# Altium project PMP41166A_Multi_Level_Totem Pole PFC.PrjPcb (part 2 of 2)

## Sheet PMP41166A_Multi_Level_Totem Pole PFC_Control Card.SchDoc
size A2; Date: Not shown in title block; ApprovedBy: Not shown in title block; CheckedBy: Not shown in title block; Author: Not shown in title block; CompanyName: Not shown in title block; Engineer: Not shown in title block; Organization: Not shown in title block; Address1: Not shown in title block; Address2: Not shown in title block; Address3: Not shown in title block; Address4: Not shown in title block; DocumentNumber: 1; Revision: Use project parameter SCH_Rev; SheetNumber: 3; SheetTotal: 4; PageSetup: Record=PageOptions¦CenterHorizontal=True¦CenterVertical=True¦PrintScale=0.69¦XCorrection=1.00¦YCorrection=1.00¦PrintKind=0¦BorderSize=5000000¦LeftOffset=0¦BottomOffset=0¦Orientation=2¦PaperLength=1000¦PaperWidth=1000¦Scale=100¦PaperSource=15¦PrintQuality=600¦MediaType=1¦DitherType=10¦PaperKind=Letter¦PrintScaleMode=1
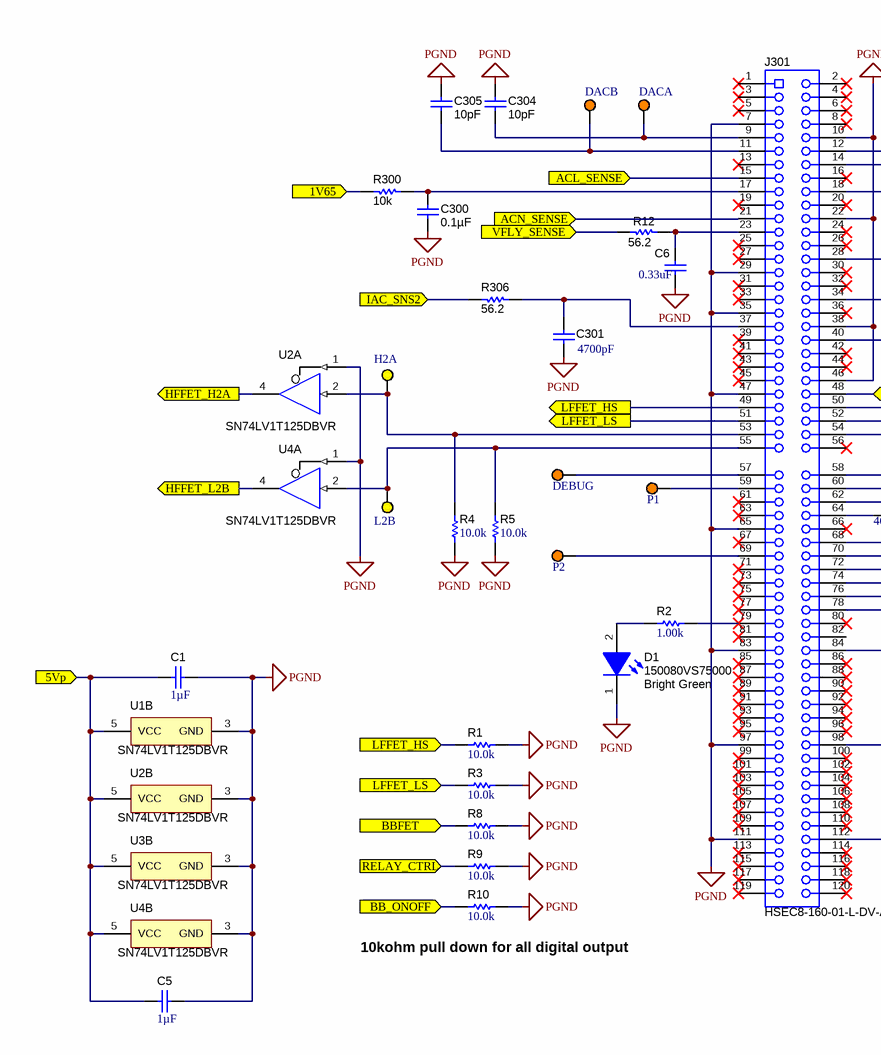
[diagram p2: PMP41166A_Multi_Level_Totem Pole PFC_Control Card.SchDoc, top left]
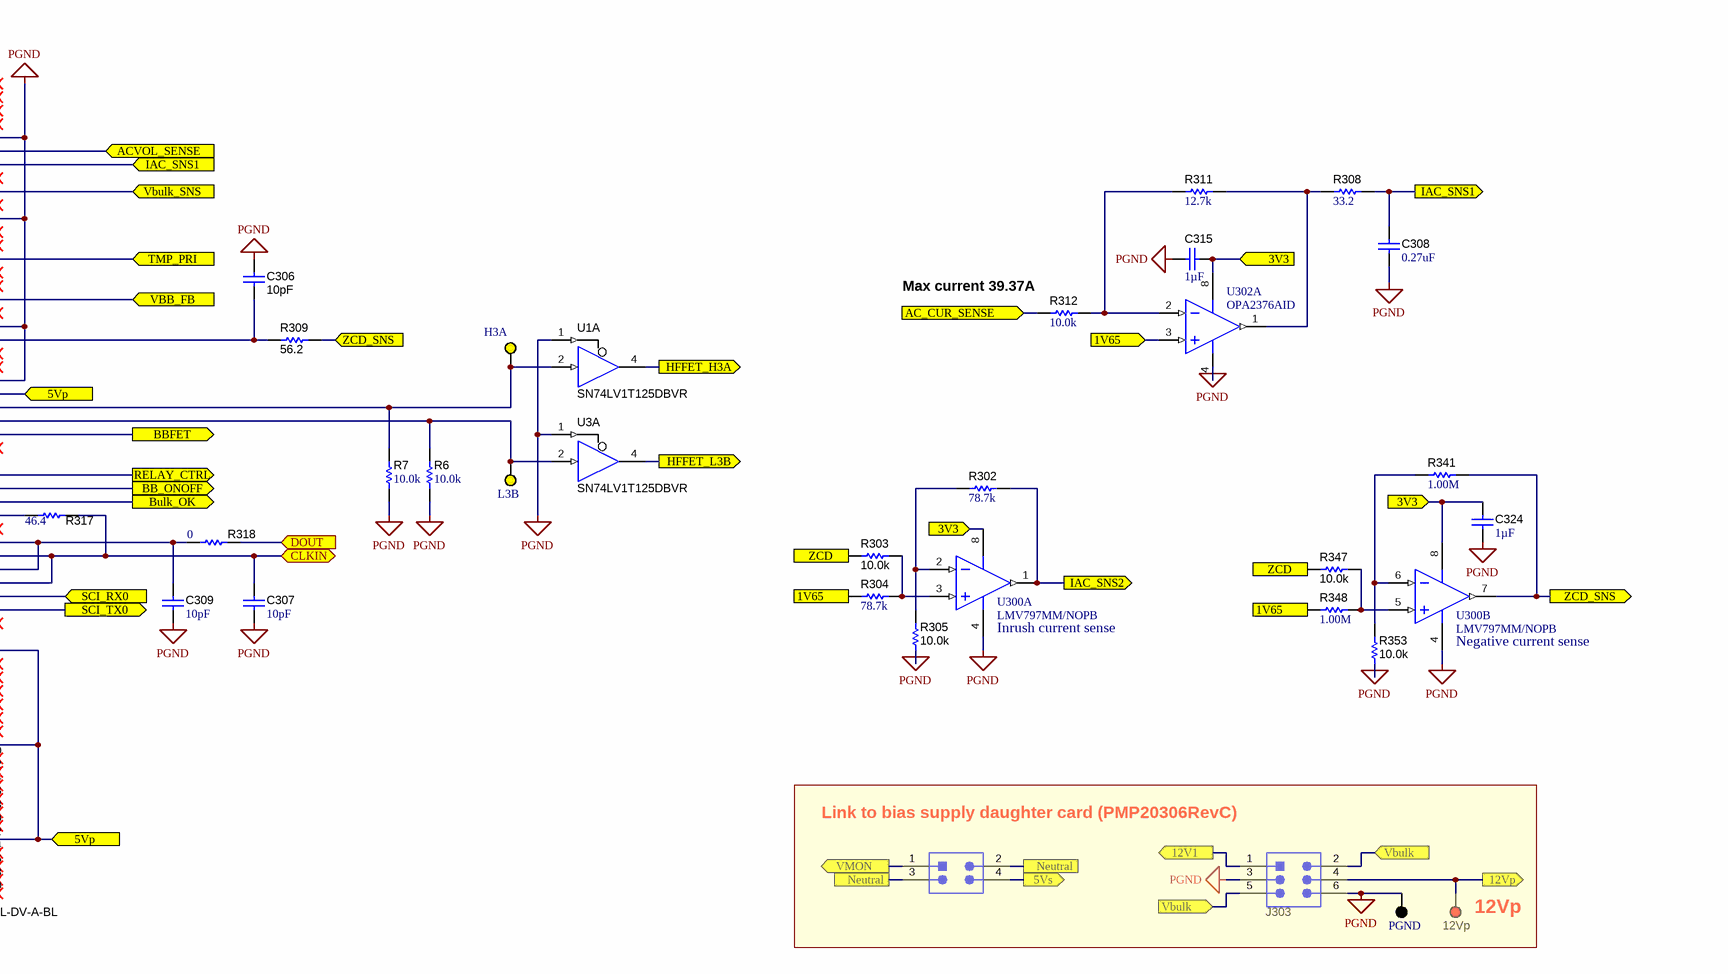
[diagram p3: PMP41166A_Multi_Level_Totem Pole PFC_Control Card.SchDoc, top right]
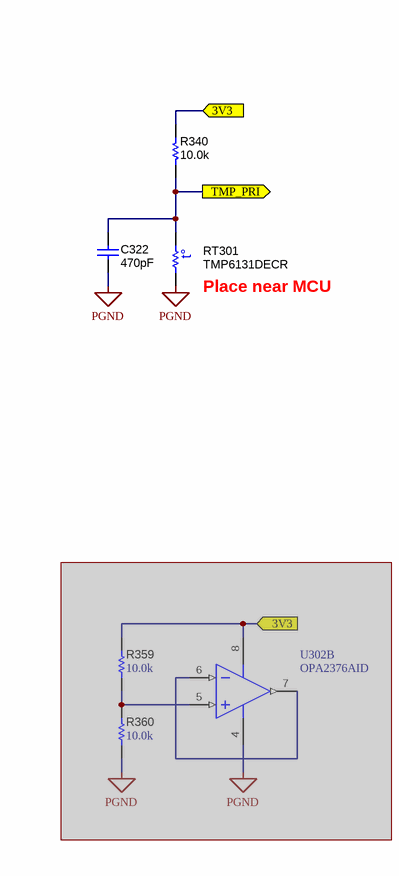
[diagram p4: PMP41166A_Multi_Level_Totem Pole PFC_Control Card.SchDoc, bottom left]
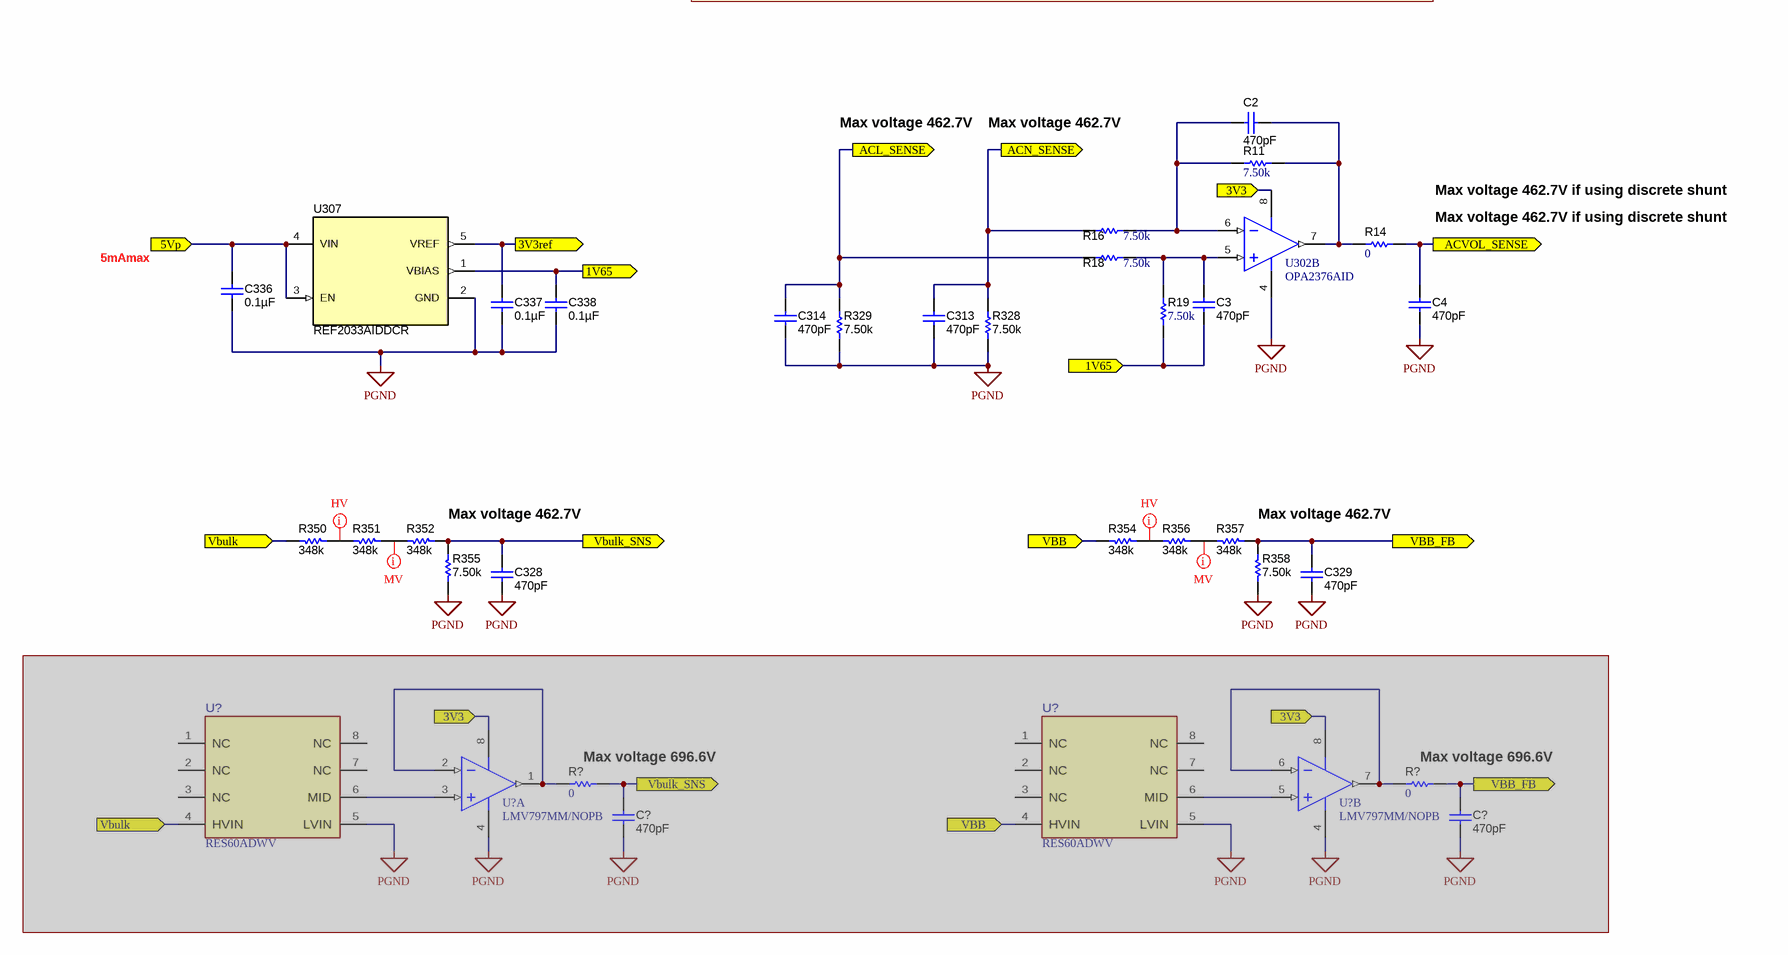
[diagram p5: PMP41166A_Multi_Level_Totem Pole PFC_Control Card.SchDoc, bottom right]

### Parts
(Parts that share a designator on the sheet are numbered #1, #2 ... from top to bottom, then left to right.)
12Vp  5000  [Keystone5000]  (value not drawn)
C1  Cap_F: 1µF  [0603]  (hidden comment: GCM188R71C105KA64J)
C2  ValueDisplayed: 470pF  [0402]  (hidden comment: CGA2B2X7R1H471K050BA)
C3  ValueDisplayed: 470pF  [0402]  (hidden comment: CGA2B2X7R1H471K050BA)
C4  ValueDisplayed: 470pF  [0402]  (hidden comment: CGA2B2X7R1H471K050BA)
C5  Cap_F: 1µF  [0603]  (hidden comment: GCM188R71C105KA64J)
C6  ValueDisplayed: 0.33uF  [0402]  (hidden comment: GRM155C80J334KE01D)
C300  ValueDisplayed: 0.1µF  [0402]  (hidden comment: GRM155R60J104KA01D)
C301  ValueDisplayed: 4700pF  [0402]  (hidden comment: GRM155R61H472KA01D)
C304  ValueDisplayed: 10pF  [0402]  (hidden comment: 04025U100CAT2A)
C305  ValueDisplayed: 10pF  [0402]  (hidden comment: 04025U100CAT2A)
C306  ValueDisplayed: 10pF  [0402]  (hidden comment: 04025U100CAT2A)
C307  ValueDisplayed: 10pF  [0402]  (hidden comment: C0402C100C8GACTU)
C308  ValueDisplayed: 0.27uF  [0402]  (hidden comment: GRM155R61A274KE15D)
C309  ValueDisplayed: 10pF  [0402]  (hidden comment: C0402C100C8GACTU)
C313  ValueDisplayed: 470pF  [0402]  (hidden comment: CGA2B2X7R1H471K050BA)
C314  ValueDisplayed: 470pF  [0402]  (hidden comment: CGA2B2X7R1H471K050BA)
C315  Cap_F: 1µF  [0603]  (hidden comment: C1608X7R1E105K080AB)
C322  ValueDisplayed: 470pF  [0402]  (hidden comment: CGA2B2X7R1H471K050BA)
C324  ValueDisplayed: 1µF  [0402]  (hidden comment: CC0402MRX5R6BB105)
C328  ValueDisplayed: 470pF  [0402]  (hidden comment: CGA2B2X7R1H471K050BA)
C329  ValueDisplayed: 470pF  [0402]  (hidden comment: CGA2B2X7R1H471K050BA)
C336  ValueDisplayed: 0.1µF  [0603]  (hidden comment: 06033C104JAT2A)
C337  ValueDisplayed: 0.1µF  [0603]  (hidden comment: 06033C104JAT2A)
C338  ValueDisplayed: 0.1µF  [0603]  (hidden comment: 06033C104JAT2A)
C?#1  ValueDisplayed: 470pF  [0402]  (hidden comment: CGA2B2X7R1H471K050BA)  (masked out: inside a compile mask, not in the netlist)
C?#2  ValueDisplayed: 470pF  [0402]  (hidden comment: CGA2B2X7R1H471K050BA)  (masked out: inside a compile mask, not in the netlist)
D1  150080VS75000  value Bright Green  [WL-SMCW_Green_0805]
DACA  5003  [Keystone5003]  (value not drawn)
DACB  5003  [Keystone5003]  (value not drawn)
DEBUG  5003  [Keystone5003]  (value not drawn)
H2A  5004  [Keystone5004]  (value not drawn)
H3A  5004  [Keystone5004]  (value not drawn)
J301  HSEC8-160-01-L-DV-A-BL  [controlCARD-120HSEC]
J302  PBC02DAAN  [Sullins_PxC02DAAN]  (value not drawn)
J303  PBC03DAAN  [Sullins_PBC03DAAN]  (value not drawn)
L2B  5004  [Keystone5004]  (value not drawn)
L3B  5004  [Keystone5004]  (value not drawn)
P1  5003  [Keystone5003]  (value not drawn)
P2  5003  [Keystone5003]  (value not drawn)
PGND#8  5  [Keystone5001]  (value not drawn)
R1  ValueDisplayed: 10.0k  [0402]  (hidden comment: RT0402BRD0710KL)
R2  ValueDisplayed: 1.00k  [0402]  (hidden comment: CRCW04021K00FKED)
R3  ValueDisplayed: 10.0k  [0402]  (hidden comment: RT0402BRD0710KL)
R4  ValueDisplayed: 10.0k  [0402]  (hidden comment: RT0402BRD0710KL)
R5  ValueDisplayed: 10.0k  [0402]  (hidden comment: RT0402BRD0710KL)
R6  ValueDisplayed: 10.0k  [0402]  (hidden comment: RT0402BRD0710KL)
R7  ValueDisplayed: 10.0k  [0402]  (hidden comment: RT0402BRD0710KL)
R8  ValueDisplayed: 10.0k  [0402]  (hidden comment: RT0402BRD0710KL)
R9  ValueDisplayed: 10.0k  [0402]  (hidden comment: RT0402BRD0710KL)
R10  ValueDisplayed: 10.0k  [0402]  (hidden comment: RT0402BRD0710KL)
R11  ValueDisplayed: 7.50k  [0402]  (hidden comment: CRCW04027K50FKED)
R12  ValueDisplayed: 56.2  [0402]  (hidden comment: CRCW040256R2FKED)
R14  ValueDisplayed: 0  [0402]  (hidden comment: CRCW04020000Z0ED)
R16  ValueDisplayed: 7.50k  [0402]  (hidden comment: CRCW04027K50FKED)
R18  ValueDisplayed: 7.50k  [0402]  (hidden comment: CRCW04027K50FKED)
R19  ValueDisplayed: 7.50k  [0402]  (hidden comment: CRCW04027K50FKED)
R300  value 10k  [0402]  (hidden comment: CRCW040210K0JNED)
R302  ValueDisplayed: 78.7k  [0402]  (hidden comment: CRCW040278K7FKED)
R303  ValueDisplayed: 10.0k  [0402]  (hidden comment: ERJPA2F1002X)
R304  ValueDisplayed: 78.7k  [0402]  (hidden comment: CRCW040278K7FKED)
R305  ValueDisplayed: 10.0k  [0402]  (hidden comment: ERJPA2F1002X)
R306  ValueDisplayed: 56.2  [0402]  (hidden comment: CRCW040256R2FKED)
R308  ValueDisplayed: 33.2  [0402]  (hidden comment: CRCW040233R2FKED)
R309  ValueDisplayed: 56.2  [0402]  (hidden comment: CRCW040256R2FKED)
R311  ValueDisplayed: 12.7k  [0402]  (hidden comment: CRCW040212K7FKED)
R312  ValueDisplayed: 10.0k  [0402]  (hidden comment: ERJ-2RKF1002X)
R317  ValueDisplayed: 46.4  [0402]  (hidden comment: CRCW040246R4FKED)
R318  ValueDisplayed: 0  [0402]  (hidden comment: CRCW04020000Z0ED)
R328  ValueDisplayed: 7.50k  [0402]  (hidden comment: CRCW04027K50FKED)
R329  ValueDisplayed: 7.50k  [0402]  (hidden comment: CRCW04027K50FKED)
R340  ValueDisplayed: 10.0k  [0402]  (hidden comment: CRCW040210K0FKED)
R341  ValueDisplayed: 1.00M  [0402]  (hidden comment: CRCW04021M00FKED)
R347  ValueDisplayed: 10.0k  [0402]  (hidden comment: ERJPA2F1002X)
R348  ValueDisplayed: 1.00M  [0402]  (hidden comment: CRCW04021M00FKED)
R350  ValueDisplayed: 348k  [1206]  (hidden comment: RC1206FR-07348KL)
R351  ValueDisplayed: 348k  [1206]  (hidden comment: RC1206FR-07348KL)
R352  ValueDisplayed: 348k  [1206]  (hidden comment: RC1206FR-07348KL)
R353  ValueDisplayed: 10.0k  [0402]  (hidden comment: ERJPA2F1002X)
R354  ValueDisplayed: 348k  [1206]  (hidden comment: RC1206FR-07348KL)
R355  ValueDisplayed: 7.50k  [0402]  (hidden comment: CRCW04027K50FKED)
R356  ValueDisplayed: 348k  [1206]  (hidden comment: RC1206FR-07348KL)
R357  ValueDisplayed: 348k  [1206]  (hidden comment: RC1206FR-07348KL)
R358  ValueDisplayed: 7.50k  [0402]  (hidden comment: CRCW04027K50FKED)
R359  ValueDisplayed: 10.0k  [0402]  (hidden comment: ERJ-2RKF1002X)  (masked out: inside a compile mask, not in the netlist)
R360  ValueDisplayed: 10.0k  [0402]  (hidden comment: ERJ-2RKF1002X)  (masked out: inside a compile mask, not in the netlist)
R?#1  ValueDisplayed: 0  [0603]  (hidden comment: RC0603JR-070RL)  (masked out: inside a compile mask, not in the netlist)
R?#2  ValueDisplayed: 0  [0603]  (hidden comment: RC0603JR-070RL)  (masked out: inside a compile mask, not in the netlist)
RT301  TMP6131DECR  [DEC0002A]
U1#1  SN74LV1T125DBVR  [DBV0005A_N]  (part A of 2)
U1#2  SN74LV1T125DBVR  [DBV0005A_N]  (part B of 2)
U2#1  SN74LV1T125DBVR  [DBV0005A_N]  (part A of 2)
U2#2  SN74LV1T125DBVR  [DBV0005A_N]  (part B of 2)
U3#1  SN74LV1T125DBVR  [DBV0005A_N]  (part A of 2)
U3#2  SN74LV1T125DBVR  [DBV0005A_N]  (part B of 2)
U4#1  SN74LV1T125DBVR  [DBV0005A_N]  (part A of 2)
U4#2  SN74LV1T125DBVR  [DBV0005A_N]  (part B of 2)
U300  LMV797MM/NOPB  [DGK0008A_N]  (parts A,B of 2)
U302#1  OPA2376AID  [D0008A_N]  (parts A,B of 2)
U302#2  OPA2376AID  [D0008A_N]  (part B of 2)  (masked out: inside a compile mask, not in the netlist)
U307  REF2033AIDDCR  [DDC0005A_N]
U?#1  RES60ADWV  [DWV0008A-MFG]  (masked out: inside a compile mask, not in the netlist)
U?#2  RES60ADWV  [DWV0008A-MFG]  (masked out: inside a compile mask, not in the netlist)
U?#3  LMV797MM/NOPB  [DGK0008A_N]  (part A of 2)  (masked out: inside a compile mask, not in the netlist)
U?#4  LMV797MM/NOPB  [DGK0008A_N]  (part B of 2)  (masked out: inside a compile mask, not in the netlist)

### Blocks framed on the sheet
12Vp: 12Vp J302 J303 PGND#8

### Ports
1V65 (in), 1V65 (out), 3V3 (in), 3V3ref (out), 5Vp (in), 5Vs (out), 12V1 (out), 12Vp (out), AC_CUR_SENSE (in), ACL_SENSE (in), ACL_SENSE (out), ACN_SENSE (in), ACN_SENSE (out), ACVOL_SENSE (in), ACVOL_SENSE (out), BB_ONOFF (in), BB_ONOFF (out), BBFET (in), BBFET (out), Bulk_OK (out), CLKIN (bidir), DOUT (in), HFFET_H2A (out), HFFET_H3A (out), HFFET_L2B (out), HFFET_L3B (out), IAC_SNS1 (in), IAC_SNS1 (out), IAC_SNS2 (in), IAC_SNS2 (out), LFFET_HS (in), LFFET_HS (out), LFFET_LS (in), LFFET_LS (out), Neutral, RELAY_CTRL (in), RELAY_CTRL (out), SCI_RX0 (in), SCI_TX0 (out), TMP_PRI (in), TMP_PRI (out), VBB (in), VBB_FB (in), VBB_FB (out), Vbulk (in), Vbulk_SNS (in), Vbulk_SNS (out), VFLY_SENSE (in), VMON (out), ZCD (in), ZCD_SNS (in), ZCD_SNS (out)

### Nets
PGND: C1.1 C4.2 C5.1 C6.2 C300.1 C301.2 C304.2 C305.2 C306.2 C307.2 C308.2 C309.2 C313.2 C314.2 C315.2 C322.2 C324.2 C328.2 C329.2 C336.1 C337.1 C338.1 D1.1(K) J301.7 J301.10 J301.22 J301.29 J301.35 J301.38 J301.46 J301.47 J301.65 J301.83 J301.97 J301.111 J303.3 J303.6 PGND#8.1 R1.2 R3.2 R4.1 R5.1 R6.2 R7.2 R8.2 R9.2 R10.2 R305.1 R328.1 R329.1 R353.1 R355.1 R358.1 RT301.1 U1#1.1(~{OE}) U1#2.3(GND) U2#1.1(~{OE}) U2#2.3(GND) U3#1.1(~{OE}) U3#2.3(GND) U4#1.1(~{OE}) U4#2.3(GND) U300.4(V-) U302#1.4(V-) U307.2(GND)
1V65: C3.2 C338.2 R19.1 R300.1 R304.1 R348.2 U302#1.3(IN_A+) U307.1(VBIAS) ; port 1V65
3V3: C315.1 C324.1 R340.1 U300.8(V+) U302#1.8(V+) ; port 3V3
3V3ref: C337.2 U307.5(VREF) ; port 3V3ref
5Vp: C1.2 C5.2 C336.2 J301.48 J301.84 J301.98 J301.112 U1#2.5(VCC) U2#2.5(VCC) U3#2.5(VCC) U4#2.5(VCC) U307.3(EN) U307.4(VIN) ; port 5Vp
5Vs: J302.4 ; port 5Vs
12V1: J303.1 ; port 12V1
12Vp: 12Vp.1 J303.4 ; port 12Vp
AC_CUR_SENSE: R312.2 ; port AC_CUR_SENSE
ACL_SENSE: C314.1 J301.15 R18.1 R329.2 ; port ACL_SENSE
ACN_SENSE: C313.1 J301.21 R16.1 R328.2 ; port ACN_SENSE
ACVOL_SENSE: C4.1 J301.12 R14.1 ; port ACVOL_SENSE
AINN: J302.2 J302.3 ; port Neutral
BB_ONOFF: J301.60 R10.1 ; port BB_ONOFF
BBFET: J301.54 R8.1 ; port BBFET
Bulk_OK: J301.62 ; port Bulk_OK
CLKIN: C307.1 J301.70 J301.74 R317.1 ; port CLKIN
DOUT: R318.2 ; port DOUT
HFFET_H2A: U2#1.4(Y) ; port HFFET_H2A
HFFET_H3A: U1#1.4(Y) ; port HFFET_H3A
HFFET_L2B: U4#1.4(Y) ; port HFFET_L2B
HFFET_L3B: U3#1.4(Y) ; port HFFET_L3B
IAC_SNS1: C308.1 J301.14 R308.2 ; port IAC_SNS1
IAC_SNS2: R302.2 R306.2 U300.1(OUTA) ; port IAC_SNS2
LFFET_HS: J301.49 R1.1 ; port LFFET_HS
LFFET_LS: J301.51 R3.1 ; port LFFET_LS
RELAY_CTRL: J301.58 R9.1 ; port RELAY_CTRL
SCI_RX0: J301.76 ; port SCI_RX0
SCI_TX0: J301.78 ; port SCI_TX0
TMP_PRI: C322.1 J301.28 R340.2 RT301.2 ; port TMP_PRI
VBB: R354.2 ; port VBB
VBB_FB: C329.1 J301.34 R357.1 R358.2 ; port VBB_FB
Vbulk: J303.2 J303.5 R350.2 ; port Vbulk
Vbulk_SNS: C328.1 J301.18 R352.1 R355.2 ; port Vbulk_SNS
VFLY_SENSE: R12.2 ; port VFLY_SENSE
VMON: J302.1 ; port VMON
ZCD: R303.1 R347.1 ; port ZCD
ZCD_SNS: R309.1 R341.2 U300.7(OUTB) ; port ZCD_SNS
NetC2_1: C2.1 R11.1 R16.2 U302#1.6(IN_B-)
NetC2_2: C2.2 R11.2 R14.2 U302#1.7(OUT_B)
NetC3_1: C3.1 R18.2 R19.2 U302#1.5(IN_B+)
NetC6_1: C6.1 J301.23 R12.1
NetC300_2: C300.2 J301.17 R300.2
NetC301_1: C301.1 J301.37 R306.1
NetC304_1: C304.1 DACA.1 J301.9
NetC305_1: C305.1 DACB.1 J301.11
NetC306_1: C306.1 J301.40 R309.2
NetC309_1: C309.1 J301.68 J301.72 R318.1
NetD1_2: D1.2(A) R2.1
NetDEBUG_1: DEBUG.1 J301.57
NetH2A_1: H2A.1 J301.53 R4.2 U2#1.2(A)
NetH3A_1: H3A.1 J301.50 R7.1 U1#1.2(A)
NetJ301_52: J301.52 L3B.1 R6.1 U3#1.2(A)
NetJ301_55: J301.55 L2B.1 R5.2 U4#1.2(A)
NetJ301_59: J301.59 P1.1
NetJ301_64: J301.64 R317.2
NetJ301_69: J301.69 P2.1
NetJ301_79: J301.79 R2.2
NetR302_1: R302.1 R305.2 U300.2(INA-)
NetR303_2: R303.2 R304.2 U300.3(INA+)
NetR308_1: R308.1 R311.2 U302#1.1(OUT_A)
NetR311_1: R311.1 R312.1 U302#1.2(IN_A-)
NetR341_1: R341.1 R353.2 U300.6(INB-)
NetR347_2: R347.2 R348.1 U300.5(INB+)
NetR350_1: R350.1 R351.2
NetR351_1: R351.1 R352.2
NetR354_1: R354.1 R356.2
NetR356_1: R356.1 R357.2

Not connected (* = marked no-connect by the designer): J301 1* 2* 3* 4* 5* 6* 8* 13* 16* 19* 20* 24* 25* 26* 27* 30* 31* 32* 33* 36* 39* 41* 42* 43* 44* 45* 56* 61* 63* 66* 67* 71* 73* 75* 77* 80* 81* 82 85* 86* 87* 88* 89* 90* 91* 92* 93* 94* 95* 96* 99* 100* 101* 102* 103* 104* 105* 106* 107* 108* 109* 110* 113* 114* 115* 116* 117* 118* 119* 120*

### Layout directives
net class MV: NetR351_1, NetR356_1
net class HV: NetR350_1, NetR354_1

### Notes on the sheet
- (near R312) Max current 39.37A
- (near U300) Inrush current sense
- (near U300) Negative current sense
- Link to bias supply daughter card (PMP20306RevC)
- (near R10) 10kohm pull down for all digital output
- Max voltage 462.7V
- (near R14) Max voltage 462.7V if using discrete shunt
- Max voltage 462.7V if using discrete shunt
- (near C336) 5mAmax
- (near RT301) Place near MCU
- (near R?#1) Max voltage 696.6V
- (near R?#2) Max voltage 696.6V

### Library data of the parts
12Vp = 5000: Test Point, Miniature, Red, TH; Manufacturer: Keystone; CompType: Test Point Loop; ContactFinish: Silver; Green_Lifecycle: Active; Green_REACh: Passed
C1 C5 = CMP-0079154-1: CAP, CERM, 1 µF, 16 V,+/- 10%, X7R, AEC-Q200 Grade 1, 0603; Manufacturer: MuRata; SizeAreaWB_mm2: 4.68; SizeArea_mm2: 1.28; AEC Qualified: Y; AEC Category: Q200; Value: 1uF; TaMax_C: 125°C; SizeZ_mm: 1; Polarized: N; TaMin_C: -55°C; SizeY_mm: 0.8; Value2: 16V; U/M: EA; SizeX_mm: 1.6
C2-C4 C313 C314 C322 C328 C329 C?#1 C?#2 = CMP-0006320-2: CAP, CERM, 470 pF, 50 V, +/- 10%, X7R, AEC-Q200 Grade 1, 0402; Manufacturer: TDK; TaMin_C: -55°C; ESR_ohm: 4.96489; Polarized: N; SizeAreaWB_mm2: 3; Value1: 4.96489 ohm; U/M: EA; Value: 470pF; TaMax_C: 125°C; SizeZ_mm: 0.6; SizeX_mm: 1; SizeY_mm: 0.5; Value2: 50V; CompType: Capacitor; AEC Qualified: Y; IRMS_A: 2.28414dA; AEC Category: Q200
C6 = CMP-0006523-2: CAP, CERM, 0.33 uF, 6.3 V, +/- 10%, X6S, 0402; Manufacturer: MuRata; TaMin_C: -55°C; Polarized: N; SizeAreaWB_mm2: 3; Value1: Unknown; U/M: EA; Value: 0.33uF; TaMax_C: 105°C; SizeZ_mm: 0.6; SizeX_mm: 1; SizeY_mm: 0.5; Cap_F: 330nF; AEC Category: Q200; Value2: 6.3V
C300 = GRM155R60J104KA01D: CAP, CERM, 0.1uF, 6.3V, +/-10%, X5R, 0402; Manufacturer: MuRata; Polarized: N; CompType: Capacitor; U/M: EA; Cap_F: 0.0000001; Tolerance_%: 10; Value1: Unknown; VDC_V: 6.3; TaMin_C: -55; TaMax_C: 85
C301 = CMP-0006616-2: CAP, CERM, 4700 pF, 50 V, +/- 10%, X5R, 0402; Manufacturer: MuRata; TaMin_C: -55°C; Polarized: N; SizeAreaWB_mm2: 3; Value1: Unknown; U/M: EA; Value: 4700pF; TaMax_C: 85°C; SizeZ_mm: 0.6; SizeX_mm: 1; SizeY_mm: 0.5; Value2: 50V; Cap_F: 4.7nF; AEC Category: Q200
C304-C306 = CMP-0064911-2: CAP, CERM, 10 pF, 50 V,+/- 2.5%, C0G/NP0, AEC-Q200 Grade 1, 0402; Manufacturer: AVX; TaMin_C: -55°C; Polarized: N; SizeAreaWB_mm2: 3; Value1: Unknown; U/M: EA; Value: 10pF; TaMax_C: 125°C; SizeZ_mm: 0.6; SizeX_mm: 1; SizeY_mm: 0.5; Value2: 50V; AEC Qualified: Y; AEC Category: Q200
C307 C309 = CMP-0064914-1: CAP, CERM, 10 pF, 10 V,+/- 2.5%, C0G/NP0, 0402; Manufacturer: Kemet; TaMin_C: -55°C; Polarized: N; SizeAreaWB_mm2: 3; Value1: Unknown; U/M: EA; Value: 10pF; TaMax_C: 125°C; SizeZ_mm: 0.6; SizeX_mm: 1; SizeY_mm: 0.5; Value2: 10V; AEC Category: Q200
C308 = CMP-0006573-2: CAP, CERM, 0.27 uF, 10 V, +/- 10%, X5R, 0402; Manufacturer: MuRata; TaMin_C: -55°C; Polarized: N; SizeAreaWB_mm2: 3; Value1: Unknown; U/M: EA; Value: 0.27uF; TaMax_C: 85°C; SizeZ_mm: 0.6; SizeX_mm: 1; SizeY_mm: 0.5; Value2: 10V; Cap_F: 270nF; AEC Category: Q200
C315 = CMP-0007040-4: CAP, CERM, 1 uF, 25 V, +/- 10%, X7R, 0603; Manufacturer: TDK; TaMin_C: -55°C; Polarized: N; SizeAreaWB_mm2: 4.68; Value1: Unknown; U/M: EA; Value: 1uF; TaMax_C: 125°C; SizeZ_mm: 1; SizeX_mm: 1.6; SizeY_mm: 0.8; Value2: 25V; SizeArea_mm2: 1.28; AEC Category: Q200
C324 = CMP-0081457-1: CAP, CERM, 1 µF, 10 V,+/- 20%, X5R, 0402; Manufacturer: Yageo America; TaMin_C: -55°C; Polarized: N; SizeAreaWB_mm2: 3; U/M: EA; Value: 1uF; TaMax_C: 85°C; SizeZ_mm: 0.6; SizeX_mm: 1; SizeY_mm: 0.5; Value2: 10V; AEC Category: Q200
C336-C338 = 06033C104JAT2A: CAP, CERM, 0.1uF, 25V, +/-5%, X7R, 0603; Manufacturer: AVX; Polarized: N; CompType: Capacitor; U/M: EA; Cap_F: 0.0000001; Tolerance_%: 5; ESR_Ohm: 0.05; Value1: 0.05 ohm; VDC_V: 25; TaMin_C: -55; TaMax_C: 125
D1 = CMP-0002960-2: LED, Bright Green, SMD; Manufacturer: Wurth Elektronik; Io_A: 20mA; Power_TotalModule: 72mW; Vr_V: 5V; Tjmax_C: 85°C; Value1: 0.072W; U/M: EA; Angle: 140; Vf_V: 2V; Type: AlInGaP
DACA DACB DEBUG P1 P2 = CMP-0055140-2: Test Point, Miniature, Orange, TH; Manufacturer: Keystone Electronics; Green_Lifecycle: Active; ContactFinish: Silver; CNHeader: FALSE; CT: TRUE; Green_REACh: Passed
H2A H3A L2B L3B = CMP-0055141-1: Test Point, Miniature, Yellow, TH; Manufacturer: Keystone; CNHeader: FALSE; Green_Lifecycle: Active; Green_REACh: Passed; ContactFinish: Silver; CT: TRUE
J301 = controlCARD-120HSEC: C2000 controlCARD-120HSEC connector, SMT; Manufacturer: Samtec; SymbolCreator: a0412235; Note: The pin numbering does not match Samtec datasheet
J302 = PBC02DAAN: Header, 2.54mm, 2x2, Gold, TH; Manufacturer: Sullins Connector Solutions; SymbolCreator: a0412235; U/M: EA
J303 = PBC03DAAN: Header, 100mil, 3x2, Gold, TH; Manufacturer: Sullins Connector Solutions; SymbolCreator: a0412235; U/M: EA
PGND#8 = CMP-0055138-1: Test Point, Miniature, Black, TH; Manufacturer: Keystone; CNHeader: FALSE; Green_Lifecycle: Active; Green_REACh: Passed; ContactFinish: Silver; CT: TRUE
R1 R3-R10 = CMP-0065360-1: RES, 10.0 k, .1%, .0625 W, 0402; Manufacturer: Yageo America; Power_W: 62.5mW; TempCo: 25 ppm/C; Value_Code: 10k0; U/M: EA; Value: 10.0k; EIA_Code: E192; Tolerance_%: 0.1%; Res_ohm: 10k; SizeX_mm: 1.0; SizeY_mm: 0.5; SizeZ_mm: 0.6; Value2: .0625W; VDC_V: 50V; AEC Category: Q200
R2 = CMP-0026071-3: RES, 1.00 k, 1%, 0.063 W, AEC-Q200 Grade 0, 0402; Manufacturer: Vishay-Dale; Power_W: 63mW; TempCo: 100 ppm/C; Value_Code: 1k00; Value: 1.00k; EIA_Code: E96; Res_ohm: 1k; SizeX_mm: 1; SizeY_mm: 0.5; SizeZ_mm: 0.6; Value2: 0.063W; AEC Qualified: Y; VDC_V: 50V; AEC Category: Q200; AEC Grade: 0
R11 R16 R18 R19 = CMP-0026555-2: RES, 7.50 k, 1%, 0.063 W, AEC-Q200 Grade 0, 0402; Manufacturer: Vishay-Dale; Power_W: 63mW; TempCo: 100 ppm/C; Value_Code: 7k50; Value: 7.50k; EIA_Code: E96; Res_ohm: 7.5k; SizeX_mm: 1; SizeY_mm: 0.5; SizeZ_mm: 0.6; Value2: 0.063W; AEC Qualified: Y; VDC_V: 50V; AEC Category: Q200; AEC Grade: 0
R12 R306 R309 = CMP-0026454-2: RES, 56.2, 1%, 0.063 W, AEC-Q200 Grade 0, 0402; Manufacturer: Vishay-Dale; Power_W: 63mW; TempCo: 100 ppm/C; Value_Code: 56R2; Value: 56.2; EIA_Code: E96; SizeX_mm: 1; SizeY_mm: 0.5; SizeZ_mm: 0.6; Value2: 0.063W; AEC Qualified: Y; VDC_V: 50V; AEC Category: Q200; AEC Grade: 0
R14 R318 = CMP-0026822-3: RES, 0, 5%, 0.063 W, AEC-Q200 Grade 0, 0402; Manufacturer: Vishay-Dale; Power_W: 63mW; TempCo: 200 ppm/C; Value_Code: 0000; Value: 0; EIA_Code: E24; SizeX_mm: 1; SizeY_mm: 0.5; SizeZ_mm: 0.6; Value2: 0.063W; AEC Qualified: Y; VDC_V: 50V; AEC Category: Q200
R300 = CRCW040210K0JNED: RES, 10k ohm, 5%, 0.063W, 0402; Manufacturer: Vishay-Dale; CompType: Resistor; Res_ohm: 10000; Value_Code: 10k0; Tolerance_%: 5; Power_W: 0.063; VDC_V: 50; TempCo: 200 ppm/C; EIA_Code: E24; U/M: EA
R302 R304 = CMP-0026551-2: RES, 78.7 k, 1%, 0.063 W, AEC-Q200 Grade 0, 0402; Manufacturer: Vishay-Dale; Power_W: 63mW; TempCo: 100 ppm/C; Value_Code: 78k7; Value: 78.7k; EIA_Code: E96; SizeX_mm: 1; SizeY_mm: 0.5; SizeZ_mm: 0.6; Value2: 0.063W; AEC Qualified: Y; VDC_V: 50V; AEC Category: Q200; AEC Grade: 0
R303 R305 R347 R353 = CMP-0078779-1: RES, 10.0 k, 1%, 0.2 W, AEC-Q200 Grade 0, 0402; Manufacturer: Panasonic; Value_Code: 10k0; SizeArea_mm2: 0.5; AEC Qualified: Y; AEC Category: Q200; Res_ohm: 10k; Value: 10.0k; SizeZ_mm: 0.6; EIA_Code: E96; TempCo: 100 ppm/C; AEC Grade: 0; Power_W: 200mW; VDC_V: 50V; Value2: 0.2W; SizeX_mm: 1
R308 = CMP-0026299-2: RES, 33.2, 1%, 0.063 W, AEC-Q200 Grade 0, 0402; Manufacturer: Vishay-Dale; Power_W: 63mW; TempCo: 100 ppm/C; Value_Code: 33R2; Value: 33.2; EIA_Code: E96; SizeX_mm: 1; SizeY_mm: 0.5; SizeZ_mm: 0.6; Value2: 0.063W; AEC Qualified: Y; VDC_V: 50V; AEC Category: Q200; AEC Grade: 0
R311 = CMP-0025993-3: RES, 12.7 k, 1%, 0.063 W, AEC-Q200 Grade 0, 0402; Manufacturer: Vishay-Dale; Power_W: 63mW; TempCo: 100 ppm/C; Value_Code: 12k7; Value: 12.7k; EIA_Code: E96; SizeX_mm: 1; SizeY_mm: 0.5; SizeZ_mm: 0.6; Value2: 0.063W; AEC Qualified: Y; VDC_V: 50V; AEC Category: Q200; AEC Grade: 0
R312 R359 R360 = CMP-0026658-1: RES, 10.0 k, 1%, 0.1 W, 0402; Manufacturer: Panasonic; Power_W: 100mW; TempCo: 100 ppm/C; Value_Code: 10k0; U/M: EA; Value: 10.0k; EIA_Code: E96; Res_ohm: 10k; SizeX_mm: 1; SizeY_mm: 0.5; SizeZ_mm: 0.6; Value2: 0.1W; VDC_V: 50V; AEC Category: Q200
R317 = CMP-0026392-2: RES, 46.4, 1%, 0.063 W, AEC-Q200 Grade 0, 0402; Manufacturer: Vishay-Dale; Power_W: 63mW; TempCo: 100 ppm/C; Value_Code: 46R4; Value: 46.4; EIA_Code: E96; SizeX_mm: 1; SizeY_mm: 0.5; SizeZ_mm: 0.6; Value2: 0.063W; AEC Qualified: Y; VDC_V: 50V; AEC Category: Q200; AEC Grade: 0
R328 R329 R355 R358 = CRCW04027K50FKED: RES, 7.50 k, 1%, 0.063 W, 0402; Manufacturer: Vishay-Dale; CompType: Resistor; Value: 7.50k; Res_ohm: 7500; Value_Code: 7k50; Tolerance_%: 1; Power_W: 0.063; Value2: 0.063W; VDC_V: 50; TempCo: 100 ppm/C; SizeArea_mm2: 0.5; SizeZ_mm: 0.6; EIA_Code: E96; U/M: EA; AEC Category: Q200
R340 = CRCW040210K0FKED: RES, 10.0 k, 1%, 0.063 W, 0402; Manufacturer: Vishay-Dale; CompType: Resistor; Value: 10.0k; Res_ohm: 10000; Value_Code: 10k0; Tolerance_%: 1; Power_W: 0.063; Value2: 0.063W; VDC_V: 50; TempCo: 100 ppm/C; SizeArea_mm2: 0.5; SizeZ_mm: 0.6; EIA_Code: E96; U/M: EA; AEC Category: Q200
R341 R348 = CMP-0026100-2: RES, 1.00 M, 1%, 0.063 W, AEC-Q200 Grade 0, 0402; Manufacturer: Vishay-Dale; Power_W: 63mW; TempCo: 100 ppm/C; Value_Code: 1M00; Value: 1.00Meg; EIA_Code: E96; Res_ohm: 1M; SizeX_mm: 1; SizeY_mm: 0.5; SizeZ_mm: 0.6; Value2: 0.063W; AEC Qualified: Y; VDC_V: 50V; AEC Category: Q200; AEC Grade: 0
R350-R352 = CMP-0018215-2: RES, 348 k, 1%, 0.25 W, 1206; Manufacturer: Yageo America; Power_W: 250mW; TempCo: 100 ppm/C; U/M: EA; Value: 348k; EIA_Code: E96; SizeX_mm: 3.2; SizeY_mm: 1.6; SizeZ_mm: 1.35; Value2: 0.25W; SizeArea_mm2: 5.12; VDC_V: 200V; AEC Category: Q200
R354 R356 R357 = CMP-0018215-2: RES, 348 k, 1%, 0.25 W, 1206; Manufacturer: Yageo America; Power_W: 250mW; TempCo: 100 ppm/C; U/M: EA; Value: 348k; EIA_Code: E96; SizeX_mm: 3.2; SizeY_mm: 1.6; SizeZ_mm: 1.35; Value2: 0.25W; SizeArea_mm2: 5.12; CompType: Resistor; VDC_V: 200V; AEC Category: Q200
R?#1 R?#2 = CMP-0025885-5: RES, 0, 5%, 0.1 W, 0603; Manufacturer: Yageo; Power_W: 100mW; TempCo: 200 ppm/C; Value_Code: 0000; Value: 0; EIA_Code: E24; SizeX_mm: 1.6; SizeZ_mm: 1; Value2: 0.1W; SizeArea_mm2: 1.28; AEC Qualified: N; VDC_V: 75V; AEC Category: Q200; SizeY_mm: 0.8; SizeAreaWB_mm2: 4.68
RT301 = CMP-0084566-1: Thermistor, DEC0002A (X1SON-2); Alternate Manufacturer: Texas Instruments; Alternate PartNumber: TMP6131DECT; CompType: IC; AEC Category: Q200; SizeX_mm: 1; AEC Qualified: N; SizeZ_mm: 0.5; SizeArea_mm2: 0.6; SizeAreaWB_mm2: 3.2
U1#1 U1#2 U2#1 U2#2 U3#1 U3#2 U4#1 U4#2 = CMP-0051320-2: Single Power Supply, Single BUFFER GATE w/ 3-State Output (active low enable), DBV0005A (SOT-23-5); Manufacturer: Texas Instruments; Schmitt Trigger: No; Voltage(Nom)(V): 1.8,2.5,3.3,5.5; Output Drive (IOL/IOH)(Max)(mA): 8/-8; Bits(#): 1; F @ Nom Voltage(Max)(Mhz): 50; Output Type: CMOS; Input Type: TTL; VCC(Min)(V): 1.6; tpd @ Nom Voltage(Max)(ns): 14.5,9.5,8.0,6.5; 3-State Output: Yes; ICC @ Nom Voltage(Max)(mA): 0.01; Rating: Catalog; Logic: True; Special Features: 1.8V to 3.3V Up Translation,3.3V to 1.8V Down Translation,5V Input Tolerant; VCC(Max)(V): 5.5; AEC Category: Q200; AEC Qualified: N; CompType: IC; SizeAreaWB_mm2: 14.82; SizeArea_mm2: 8.12; SizeX_mm: 2.8; SizeY_mm: 2.9; SizeZ_mm: 1.45
U300 U?#3 U?#4 = CMP-0068783-2: 17 MHz, Low Noise, CMOS Input, 1.8V Operational Amplifiers, DGK0008A (VSSOP-8); Manufacturer: Texas Instruments; CompType: IC; AEC Category: Q200; AEC Qualified: N; SizeAreaWB_mm2: 23.6; SizeArea_mm2: 14.7; SizeX_mm: 4.9; SizeY_mm: 3; SizeZ_mm: 1.1
U302#1 U302#2 = CMP-0040811-1: Precision, Low Noise, Low Quiescent Current Operational Amplifier, 2 to 5.5 V, -40 to 125 degC, 8-pin SOIC (D8), Green (RoHS & no Sb/Br); Manufacturer: Texas Instruments; Total Supply Voltage(Min)(+5V is 5, +/-5V is 10): 2; Vn at 1kHz(Typ)(nV/rtHz): 7.5; CMRR(Min)(dB): 76; Sub Family: Low Input Bias Current Amp (<=10pA), Low Noise Amp (<=10nV/rtHz), Low Offset Voltage Amplifier (<=500uV), Low Supply Voltage Amplifier (<=2.7V), Precision Amplifier; Iq per channel(Max)(mA): 0.95; Total Supply Voltage(Max)(+5V is 5, +/-5V is 10): 5.5; Vio (25C)(Max)(mV): 0.025; IIB(Max)(pA): 10; Offset Drift(Typ)(uV/C): 0.32
U307 = CMP-0066190-1: Low-Drift, Low-Power, Dual-Output VREF and VREF/2 Voltage Reference, DDC0005A (SOT-23-T-5); Alternate PartNumber: REF2033AIDDCT; Alternate Manufacturer: Texas Instruments; SizeAreaWB_mm2: 14.82; U/M: EA; SizeZ_mm: 1.1; SizeX_mm: 2.8; SizeY_mm: 2.9; SizeArea_mm2: 8.12; CompType: IC
U?#1 U?#2 = CMP-0121043-1: Manufacturer: Texas Instruments; SizeZ_mm: 2.8mm; AEC Qualified: No; Standoff Height: 0.36mm

## Sheet PMP41166A_Multi_Level_Totem Pole PFC_Hardware.SchDoc
size 431 x 279 mm; Date: Not shown in title block; ApprovedBy: Not shown in title block; CheckedBy: Not shown in title block; Author: Not shown in title block; CompanyName: Not shown in title block; Engineer: Not shown in title block; Organization: Not shown in title block; Address1: Not shown in title block; Address2: Not shown in title block; Address3: Not shown in title block; Address4: Not shown in title block; DocumentNumber: 3; Revision: Use project parameter SCH_Rev; SheetNumber: 5; SheetTotal: 5; PageSetup: Record=PageOptions¦CenterHorizontal=True¦CenterVertical=True¦PrintScale=1.00¦XCorrection=1.00¦YCorrection=1.00¦PrintKind=0¦BorderSize=5000000¦LeftOffset=0¦BottomOffset=0¦Orientation=2¦PaperLength=1000¦PaperWidth=1000¦Scale=100¦PaperSource=15¦PrintQuality=600¦MediaType=1¦DitherType=10¦PaperKind=Letter¦PrintScaleMode=1
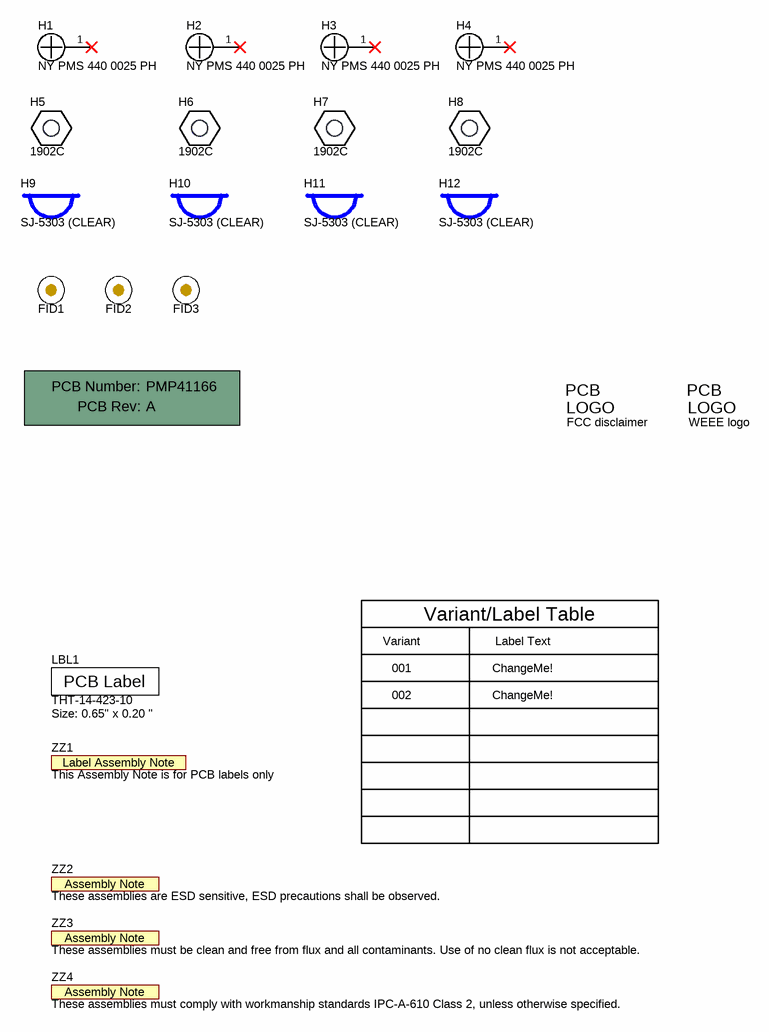
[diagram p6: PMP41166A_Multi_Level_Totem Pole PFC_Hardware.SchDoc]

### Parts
!PCB  Printed Circuit Board  (value not drawn)  (mechanical)
FID1  Fiducial  [Fiducial10-20]  (value not drawn)
FID2  Fiducial  [Fiducial10-20]  (value not drawn)
FID3  Fiducial  [Fiducial10-20]  (value not drawn)
H1  NY PMS 440 0025 PH  [NY PMS 440 0025 PH]
H2  NY PMS 440 0025 PH  [NY PMS 440 0025 PH]
H3  NY PMS 440 0025 PH  [NY PMS 440 0025 PH]
H4  NY PMS 440 0025 PH  [NY PMS 440 0025 PH]
H5  1902C  [Keystone_1902C]
H6  1902C  [Keystone_1902C]
H7  1902C  [Keystone_1902C]
H8  1902C  [Keystone_1902C]
H9  SJ-5303 (CLEAR)  [Bumpon_SJ5003Transparent]
H10  SJ-5303 (CLEAR)  [Bumpon_SJ5003Transparent]
H11  SJ-5303 (CLEAR)  [Bumpon_SJ5003Transparent]
H12  SJ-5303 (CLEAR)  [Bumpon_SJ5003Transparent]
LBL1  THT-14-423-10  Note: Size: 0.65" x 0.20 "  [Label_650x200]
Logo3  FCC disclaimer  [FCC_disclaimer]  (no BOM)
Logo4  WEEE logo  [WEEE_Minimum]  (no BOM)
ZZ1  This Assembly Note is for PCB labels only  [AssemblyNoteLabel]  (no BOM)
ZZ2  These assemblies are ESD sensitive, ESD precautions shall be observed.  [AssemblyNote]  (no BOM)
ZZ3  These assemblies must be clean and free from flux and all contaminants. Use of no clean flux is not acceptable.  [AssemblyNote]  (no BOM)
ZZ4  These assemblies must comply with workmanship standards IPC-A-610 Class 2, unless otherwise specified.  [AssemblyNote]  (no BOM)

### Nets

Not connected (* = marked no-connect by the designer): H1 1*; H2 1*; H3 1*; H4 1*

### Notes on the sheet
- Variant
- Variant/Label Table
- Label Text
- 001
- 002
- ChangeMe!

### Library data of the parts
!PCB = CMP-0003618-2: Manufacturer: Any; PartNumber: PMP41166
FID1-FID3 = CMP-0077181-1: Fiducial mark.  There is nothing to buy or mount.
H1-H4 = CMP-0003617-1: Machine Screw, Round, #4-40 x 1/4, Nylon, Philips panhead; Manufacturer: B&F Fastener Supply; CompType: Hardware
H5-H8 = CMP-0003610-1: Standoff, Hex, 0.5"L #4-40 Nylon; Manufacturer: Keystone; CompType: Hardware
H9-H12 = CMP-0003620-1: Bumpon, Hemisphere, 0.44 X 0.20, Clear; Manufacturer: 3M
LBL1 = CMP-0003625-1: Thermal Transfer Printable Labels, 0.650" W x 0.200" H - 10,000 per roll; Manufacturer: Brady; CompType: Label
Logo3 = CMP-0074847-1: FCC_disclaimer; Library Reference: Logo
Logo4 = CMP-0074769-1
ZZ1 = CMP-0003616-3
ZZ2 = CMP-0077236-1
ZZ3 = CMP-0077237-1
ZZ4 = CMP-0077238-1

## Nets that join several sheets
PGND: PMP41166A_Multi_Level_Totem Pole PFC_Main Board (54 pins), PMP41166A_Multi_Level_Totem Pole PFC_Control Card (65 pins)
3V3: PMP41166A_Multi_Level_Totem Pole PFC_Main Board (11 pins), PMP41166A_Multi_Level_Totem Pole PFC_Control Card (5 pins)
5Vp: PMP41166A_Multi_Level_Totem Pole PFC_Main Board (12 pins), PMP41166A_Multi_Level_Totem Pole PFC_Control Card (13 pins)
5Vs: PMP41166A_Multi_Level_Totem Pole PFC_Main Board (C129.1 C142.1 U104.1), PMP41166A_Multi_Level_Totem Pole PFC_Control Card (J302.4)
12V1: PMP41166A_Multi_Level_Totem Pole PFC_Main Board (C122.2 C131.1 U102.11 U102.16), PMP41166A_Multi_Level_Totem Pole PFC_Control Card (J303.1)
12Vp: PMP41166A_Multi_Level_Totem Pole PFC_Main Board (11 pins), PMP41166A_Multi_Level_Totem Pole PFC_Control Card (12Vp.1 J303.4)
AC_CUR_SENSE: PMP41166A_Multi_Level_Totem Pole PFC_Main Board (U100.6), PMP41166A_Multi_Level_Totem Pole PFC_Control Card (R312.2)
ACL_SENSE: PMP41166A_Multi_Level_Totem Pole PFC_Main Board (R101.1), PMP41166A_Multi_Level_Totem Pole PFC_Control Card (C314.1 J301.15 R18.1 R329.2)
ACN_SENSE: PMP41166A_Multi_Level_Totem Pole PFC_Main Board (R105.1), PMP41166A_Multi_Level_Totem Pole PFC_Control Card (C313.1 J301.21 R16.1 R328.2)
AINN: PMP41166A_Multi_Level_Totem Pole PFC_Main Board (7 pins), PMP41166A_Multi_Level_Totem Pole PFC_Control Card (J302.2 J302.3)
BB_ONOFF: PMP41166A_Multi_Level_Totem Pole PFC_Main Board (R139.1), PMP41166A_Multi_Level_Totem Pole PFC_Control Card (J301.60 R10.1)
BBFET: PMP41166A_Multi_Level_Totem Pole PFC_Main Board (R144.1), PMP41166A_Multi_Level_Totem Pole PFC_Control Card (J301.54 R8.1)
CLKIN: PMP41166A_Multi_Level_Totem Pole PFC_Main Board (R117.2), PMP41166A_Multi_Level_Totem Pole PFC_Control Card (C307.1 J301.70 J301.74 R317.1)
DOUT: PMP41166A_Multi_Level_Totem Pole PFC_Main Board (R118.2), PMP41166A_Multi_Level_Totem Pole PFC_Control Card (R318.2)
HFFET_H2A: PMP41166A_Multi_Level_Totem Pole PFC_Main Board (J100.1), PMP41166A_Multi_Level_Totem Pole PFC_Control Card (U2#1.4)
HFFET_H3A: PMP41166A_Multi_Level_Totem Pole PFC_Main Board (J100.5), PMP41166A_Multi_Level_Totem Pole PFC_Control Card (U1#1.4)
HFFET_L2B: PMP41166A_Multi_Level_Totem Pole PFC_Main Board (J100.8), PMP41166A_Multi_Level_Totem Pole PFC_Control Card (U4#1.4)
HFFET_L3B: PMP41166A_Multi_Level_Totem Pole PFC_Main Board (J100.4), PMP41166A_Multi_Level_Totem Pole PFC_Control Card (U3#1.4)
LFFET_HS: PMP41166A_Multi_Level_Totem Pole PFC_Main Board (R136.1), PMP41166A_Multi_Level_Totem Pole PFC_Control Card (J301.49 R1.1)
LFFET_LS: PMP41166A_Multi_Level_Totem Pole PFC_Main Board (R134.1), PMP41166A_Multi_Level_Totem Pole PFC_Control Card (J301.51 R3.1)
RELAY_CTRL: PMP41166A_Multi_Level_Totem Pole PFC_Main Board (R137.1), PMP41166A_Multi_Level_Totem Pole PFC_Control Card (J301.58 R9.1)
VBB: PMP41166A_Multi_Level_Totem Pole PFC_Main Board (7 pins), PMP41166A_Multi_Level_Totem Pole PFC_Control Card (R354.2)
Vbulk: PMP41166A_Multi_Level_Totem Pole PFC_Main Board (18 pins), PMP41166A_Multi_Level_Totem Pole PFC_Control Card (J303.2 J303.5 R350.2)
VFLY_SENSE: PMP41166A_Multi_Level_Totem Pole PFC_Main Board (J100.7), PMP41166A_Multi_Level_Totem Pole PFC_Control Card (R12.2)
ZCD: PMP41166A_Multi_Level_Totem Pole PFC_Main Board (13 pins), PMP41166A_Multi_Level_Totem Pole PFC_Control Card (R303.1 R347.1)

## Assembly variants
001: not fitted FID1 FID2 FID3 R16 R18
